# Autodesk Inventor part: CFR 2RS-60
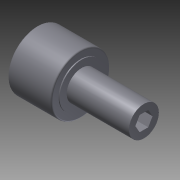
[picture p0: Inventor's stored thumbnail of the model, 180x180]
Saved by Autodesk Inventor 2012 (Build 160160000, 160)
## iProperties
Created: 2009-01
Part Number: CFR 2RS-60
Material: Steel, Mild
Document SubType Name: Modeling
Mass: 458.851 g
Surface Area: 100.794 cm^2
Volume: 58.3779 cm^3
Density: 7.86 g/cm^3
Title: Cam Follower
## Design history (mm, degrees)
sketch "Sketch1"
  geometry: L1 (0, 0)-(-35.8, 0); L2 (-35.8, 0)-(-35.8, 23.5); L3 (-35.8, 23.5)-(-0.8, 23.5); L4 (-0.8, 23.5)-(-0.8, 0); L5 (0, 0)-(50, 0); L6 (50, 0)-(50, 12); L7 (50, 12)-(0, 12); L8 (0, 12)-(0, 0); L9 (0, 0)-(-0.8, 0); L10 (-0.8, 0)-(-0.8, 17.75); L11 (-0.8, 17.75)-(0, 17.75); L12 (0, 17.75)-(0, 0); L13 (-35.8, 0)-(-36.6, 0); L14 (-36.6, 0)-(-36.6, 17.75); L15 (-36.6, 17.75)-(-35.8, 17.75); L16 (-35.8, 17.75)-(-35.8, 0)
  constraints: 32 end point, 8 parallel, 4 horizontal, 4 perpendicular, 2 collinear, 2 point on line, 1 other
  dimensions: "d1" = 47 diameter of L3 L1; "WD" = 35 distance of L2.end L3.end; "SD" = 24 diameter of L7 L1; "EL" = 0.8 distance of L10.end L11.end; "SL" = 50 distance of L6.end L7.end
revolve "Revolution1" sketch "Sketch1" stored, may be unused: angle "d4" = 90 deg
fillet "Fillet1" dims "d19" = 1
sketch "Sketch5"
  geometry: L1 (-36.6, -17.75)-(-36.6, 17.75) reference; L2 (-39.6, 0)-(-36.6, 0); C1 r 13.313 at (-39.6, 0)
  constraints: 2 end point, 1 centre point, 1 coincident, 1 midpoint, 1 perpendicular
  dimensions: "d23" = 35.5 distance of L1.start L1.end (derived); "d24" = 26.625 diameter of C1 (= 0.75 x d23); "d25" = 3 distance from line of L1 C1.centre
extrude "Extrusion3" cut sketch "Sketch5" stored distance "d20" = 3; taper "d21" = 0 deg
hole "Hole1" diameter "HEX" = 12; stored, may be unused: countersink angle "d33" = 90 deg, drill point angle "d35" = 118 deg; dims "d30" = 6, "d31" = 4, "d32" = 2, "d34" = 12 (= HEX), "d40" = 10, "d41" = 10
sketch "Sketch6"
  geometry: L1 (-6, 3.464)-(0, 6.928); L2 (0, 6.928)-(6, 3.464); L3 (6, 3.464)-(6, -3.464); L4 (6, -3.464)-(0, -6.928); L5 (0, -6.928)-(-6, -3.464); L6 (-6, -3.464)-(-6, 3.464); C1 r 6 at (0, 0) reference; 1 further point
  constraints: 12 end point, 1 coincident, 1 tangent, 1 vertical, 13 other
extrude "Extrusion4" cut sketch "Sketch6" distance "d36" = 12 (= HEX); taper "d37" = 0 deg
body "Solid1"
other parameters: "UnitMultiplier" = 25.4 [user parameter]
